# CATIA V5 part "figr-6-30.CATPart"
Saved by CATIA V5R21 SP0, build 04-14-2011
Part number: Part1
Bounding box of the stored display mesh (mm): x -61 to 61, y 0 to 173.636, z 0 to 130.49
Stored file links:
  D:\CATIA V5R21 E-RESOURCES\CATIA-V5R21\catia-v5r21-prt\c06-catia-v5r21-prt\c06-catia-v5r21-figr-6-30.CATPart
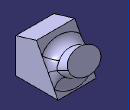
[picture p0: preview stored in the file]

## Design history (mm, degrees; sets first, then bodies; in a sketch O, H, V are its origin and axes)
Body1 (main body)
  Sketch1 on yz-plane, origin (0, 0, 0), H (0, 1, 0), V (0, 0, 1)
    line L1 (0, 0) -> (0, 110.5903)
    line L2 (0, 110.5903) -> (66.2814, 130.4899)
    line L3 (66.2814, 130.4899) -> (135.1646, 0)
    point P3 (135.1646, 0)
    line L4 (135.1646, 0) -> (0, 0)
    vertical: L1 V
    coincidence: P3 H
    horizontal: L4 H
  Pad1: profile Sketch1, direction (1, 0, 0), length 61, mirrored extent
  Sketch2 on face of Pad1, origin (0, 105.7081, 55.8014), H (-1, 0, 0), V (0, -0.4668, 0.8843)
    point P1 (0, 4.9672)
    ellipse A1 centre (0, 4.9672) semi-axes 50.9663, 34.9201 rotation 0
    coincidence: P1 V
  Pad2: profile Sketch2, direction (0, 0.8843, 0.4668), length 61
  Fillet1: radius 29, on edge [face of Pad1 | face of Pad2]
